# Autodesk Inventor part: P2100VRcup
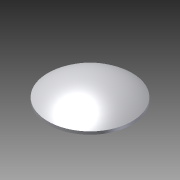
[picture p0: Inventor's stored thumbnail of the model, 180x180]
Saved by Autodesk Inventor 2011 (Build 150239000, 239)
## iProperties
Created: 2014-07
Part Number: P2100VRcup
Document SubType Name: Modeling
Designer: Evgeny
Density: 1 g/cm^3
Author: Evgeny
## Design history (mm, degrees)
sketch "Эскиз2"
  geometry: L1 (71.998, 87.093)-(71.998, 82.563); L2 (71.998, 82.563)-(72.998, 82.563); L3 (72.998, 82.563)-(72.998, 87.563); L4 (0, 113)-(0, 114); A1 r 114 centre (0, 0) between (72.998, 87.563) and (0, 114); A2 r 113 centre (0, 0) between (71.998, 87.093) and (0, 113); 2 further points
  constraints: 8 end point, 4 point on circle, 2 centre point, 2 coincident, 2 parallel
  dimensions: "d8" = 72 distance from line of point (0, 0) L1; "d9" = 1 distance between parallel lines of L3 L1; "d10" = 5 distance from line of L2 L3.end; "d11" = 113 radius of A2; "d12" = 114 radius of A1
revolve "Вращение2" sketch "Эскиз2" stored, may be unused: angle "d13" = 90 deg
node "Твердое тело2"
